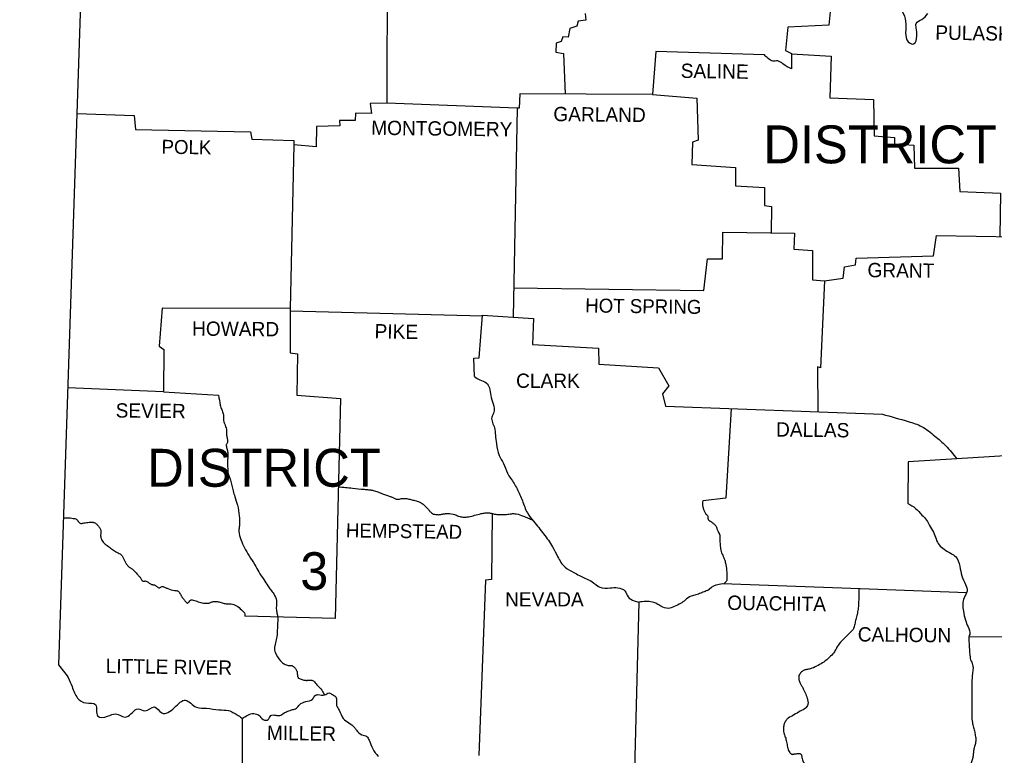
# Model space of a CAD drawing. Extents: x 982240 to 1103002, y 974866 to 1054902.
# Drawn here: x 1076997 to 1087558, y 1031353 to 1039317 of the extents above; entities that cross this region are included whole.
import ezdxf

# ---------------------------------------------------------------- set-up
doc = ezdxf.new("R2010")
doc.units = 0
doc.layers.add('1', color=7, linetype='Continuous')
doc.layers.add('Default', color=7, linetype='Continuous')

msp = doc.modelspace()

# ---------------------------------------------------------------- linework, layer by layer
at = {"layer": '1'}
msp.add_line((1082386, 1038358), (1082345, 1036097), dxfattribs=at)
for points in [[(1076997, 1048082), (1077743, 1042099), (1077419, 1032332)], [(1080980, 1039887), (1080975, 1038412), (1080795, 1038409), (1080810, 1038301), (1080637, 1038304), (1080633, 1038225), (1080464, 1038225), (1080468, 1038167), (1080216, 1038160), (1080212, 1037941), (1079967, 1037962), (1079928, 1036191), (1078542, 1036195), (1078509, 1035784), (1078560, 1035748), (1078556, 1035287), (1077518, 1035333)], [(1086498, 1039485), (1086238, 1039514), (1086249, 1039417), (1085778, 1039399), (1085763, 1039258), (1085320, 1039233), (1085295, 1038981), (1085360, 1038949), (1085360, 1038783)], [(1085065, 1038934), (1083888, 1038970), (1083855, 1038506), (1082415, 1038513), (1082409, 1038357)], [(1085716, 1036490), (1085918, 1036519), (1085932, 1036641), (1086051, 1036663), (1086058, 1036735), (1086897, 1036760), (1086930, 1036979), (1087790, 1036965)], [(1085716, 1036490), (1085673, 1035547), (1085641, 1035557), (1085644, 1035072)], [(1079928, 1036166), (1082011, 1036111)], [(1081926, 1035453), (1081918, 1035651), (1081976, 1035655), (1082012, 1036119), (1082566, 1036083), (1082552, 1035799), (1083268, 1035759), (1083272, 1035586), (1083920, 1035547), (1084032, 1035352), (1083963, 1035266), (1083996, 1035133), (1086343, 1035046)], [(1087675, 1034596), (1087148, 1034564)], [(1083704, 1033012), (1083657, 1031198), (1083171, 1031230), (1083168, 1031097), (1082527, 1031134)], [(1079409, 1031752), (1079416, 1028840), (1092610, 1028818)]]:
    msp.add_lwpolyline(points, dxfattribs=at)
for points in [[(1086498, 1039485), (1086559, 1039406), (1086595, 1039298), (1086595, 1039175), (1086624, 1039075), (1086681, 1039053), (1086717, 1039139), (1086710, 1039226), (1086710, 1039276), (1086771, 1039319), (1086836, 1039381)], [(1085360, 1038783), (1085266, 1038837), (1085212, 1038869), (1085155, 1038866), (1085108, 1038895), (1085065, 1038934)], [(1081926, 1035453), (1081983, 1035417), (1082052, 1035385), (1082088, 1035331), (1082102, 1035248), (1082127, 1035158), (1082134, 1035064), (1082113, 1035014), (1082142, 1034899), (1082152, 1034819), (1082163, 1034726), (1082192, 1034600), (1082239, 1034513), (1082282, 1034409), (1082354, 1034297), (1082415, 1034175), (1082444, 1034110), (1082498, 1033977), (1082566, 1033887), (1082674, 1033750), (1082772, 1033610), (1082826, 1033505), (1082908, 1033390), (1083002, 1033333), (1083121, 1033271), (1083196, 1033235), (1083283, 1033174), (1083394, 1033167), (1083477, 1033167), (1083553, 1033135), (1083589, 1033070), (1083654, 1033027), (1083704, 1033012)], [(1086343, 1035046), (1086624, 1034967), (1086768, 1034913), (1086912, 1034809), (1087030, 1034704), (1087148, 1034564)], [(1077419, 1032332), (1077523, 1032195), (1077566, 1032098), (1077627, 1031972), (1077717, 1031921), (1077822, 1031903), (1077843, 1031781), (1077951, 1031777), (1078038, 1031803), (1078157, 1031770), (1078283, 1031857), (1078355, 1031835), (1078459, 1031878), (1078538, 1031813), (1078675, 1031871), (1078797, 1031950), (1078913, 1031875), (1079024, 1031864), (1079157, 1031846), (1079262, 1031839), (1079355, 1031792), (1079402, 1031759), (1079409, 1031752)]]:
    msp.add_spline(points, degree=3, dxfattribs=at)
at = {"layer": 'Default'}
for points in [[(1083124, 1039384), (1083132, 1039309), (1083049, 1039301), (1083034, 1039244), (1082959, 1039222), (1082941, 1039125), (1082883, 1039129), (1082865, 1039078), (1082811, 1039060), (1082808, 1038963), (1082890, 1038949), (1082906, 1038511)], [(1085360, 1038947), (1085788, 1038920), (1085774, 1038470), (1086246, 1038452), (1086253, 1038059), (1086476, 1038041), (1086476, 1037973), (1086685, 1037959), (1086692, 1037707), (1087167, 1037707), (1087182, 1037458), (1087621, 1037437), (1087617, 1036968)], [(1083855, 1038506), (1084334, 1038466), (1084348, 1038013), (1084287, 1037991), (1084280, 1037750), (1084752, 1037717), (1084752, 1037519), (1085065, 1037501), (1085068, 1037303), (1085144, 1037293), (1085140, 1037008)], [(1082386, 1038358), (1080975, 1038412)], [(1077617, 1038301), (1078239, 1038279), (1078254, 1038128), (1079499, 1038103), (1079514, 1038023), (1079967, 1038009), (1079967, 1037962)], [(1082409, 1038357), (1082386, 1038358)], [(1082350, 1036414), (1084410, 1036385), (1084449, 1036727), (1084611, 1036727), (1084615, 1037015), (1085392, 1037005), (1085385, 1036832), (1085587, 1036817), (1085587, 1036501), (1085716, 1036490), (1085715, 1036457)], [(1079928, 1036191), (1079928, 1035712), (1080007, 1035698), (1080000, 1035251), (1080475, 1035215), (1080417, 1032836), (1079438, 1032861)], [(1078556, 1035287), (1079154, 1035251)], [(1084704, 1035107), (1084647, 1034139), (1084399, 1034110)], [(1087150, 1034564), (1086624, 1034531), (1086620, 1034081)], [(1082116, 1033972), (1082109, 1033257), (1082044, 1033250), (1081972, 1031353)], [(1084611, 1033214), (1086102, 1033160), (1087258, 1033115)], [(1087279, 1032638), (1088906, 1032641)]]:
    msp.add_lwpolyline(points, dxfattribs=at)
for points in [[(1079154, 1035251), (1079172, 1035143), (1079178, 1035120), (1079188, 1035097), (1079197, 1035073), (1079204, 1035050), (1079206, 1035032), (1079206, 1035014), (1079206, 1034996), (1079208, 1034978), (1079215, 1034951), (1079225, 1034924), (1079234, 1034897), (1079240, 1034870), (1079240, 1034830), (1079242, 1034810), (1079246, 1034790), (1079249, 1034771), (1079251, 1034751), (1079249, 1034740), (1079244, 1034729), (1079239, 1034719), (1079237, 1034708), (1079240, 1034686), (1079246, 1034665), (1079252, 1034643), (1079255, 1034621), (1079251, 1034557), (1079251, 1034503), (1079255, 1034413), (1079259, 1034392), (1079268, 1034373), (1079276, 1034353), (1079283, 1034333), (1079312, 1034215), (1079330, 1034153), (1079359, 1034060), (1079377, 1033945), (1079380, 1033858), (1079379, 1033838), (1079376, 1033819), (1079374, 1033799), (1079373, 1033779), (1079395, 1033689), (1079434, 1033599), (1079485, 1033513), (1079546, 1033415), (1079589, 1033340), (1079643, 1033257), (1079686, 1033189), (1079702, 1033167), (1079719, 1033146), (1079735, 1033124), (1079751, 1033102), (1079780, 1033030), (1079782, 1033005), (1079781, 1032980), (1079779, 1032955), (1079780, 1032929), (1079784, 1032906), (1079788, 1032883), (1079793, 1032859), (1079794, 1032836), (1079791, 1032731), (1079784, 1032638), (1079779, 1032605), (1079771, 1032573), (1079763, 1032540), (1079758, 1032508), (1079776, 1032447), (1079845, 1032357), (1079888, 1032332), (1079907, 1032327), (1079926, 1032327), (1079946, 1032325), (1079964, 1032317), (1079985, 1032294), (1080000, 1032267), (1080005, 1032248), (1080007, 1032227), (1080010, 1032208), (1080014, 1032199), (1080021, 1032191), (1080058, 1032174), (1080097, 1032166), (1080107, 1032165), (1080118, 1032166), (1080141, 1032168), (1080162, 1032168), (1080180, 1032159), (1080219, 1032116), (1080273, 1032058), (1080300, 1032008)], [(1080452, 1034261), (1080604, 1034247), (1080730, 1034233), (1080779, 1034229), (1080804, 1034226), (1080816, 1034224), (1080828, 1034222), (1080853, 1034214), (1080879, 1034205), (1080928, 1034186), (1081018, 1034153), (1081033, 1034147), (1081047, 1034141), (1081061, 1034134), (1081076, 1034128), (1081100, 1034126), (1081124, 1034130), (1081149, 1034135), (1081173, 1034135), (1081215, 1034128), (1081256, 1034117), (1081304, 1034105), (1081327, 1034096), (1081339, 1034091), (1081350, 1034085), (1081386, 1034056), (1081418, 1034024), (1081428, 1034012), (1081438, 1034000), (1081461, 1033977), (1081481, 1033966), (1081502, 1033961), (1081544, 1033959), (1081561, 1033961), (1081578, 1033965), (1081595, 1033968), (1081612, 1033970), (1081695, 1033963), (1081719, 1033956), (1081742, 1033947), (1081765, 1033939), (1081789, 1033934), (1081808, 1033932), (1081827, 1033932), (1081864, 1033937), (1081926, 1033952), (1081998, 1033970), (1082042, 1033977), (1082065, 1033978), (1082088, 1033977), (1082105, 1033974), (1082122, 1033970), (1082139, 1033966), (1082156, 1033963), (1082201, 1033960), (1082246, 1033959), (1082272, 1033961), (1082298, 1033965), (1082324, 1033969), (1082337, 1033970), (1082350, 1033970), (1082377, 1033967), (1082455, 1033944), (1082507, 1033922), (1082557, 1033899)], [(1084399, 1034110), (1084395, 1034076), (1084396, 1034059), (1084399, 1034042), (1084403, 1034025), (1084409, 1034009), (1084416, 1033993), (1084424, 1033977), (1084430, 1033969), (1084436, 1033962), (1084443, 1033956), (1084449, 1033948), (1084453, 1033937), (1084453, 1033924), (1084455, 1033912), (1084457, 1033906), (1084460, 1033901), (1084468, 1033895), (1084476, 1033890), (1084484, 1033885), (1084492, 1033880), (1084499, 1033875), (1084505, 1033870), (1084518, 1033860), (1084530, 1033850), (1084535, 1033843), (1084539, 1033837), (1084546, 1033822), (1084552, 1033806), (1084558, 1033791), (1084564, 1033775), (1084574, 1033756), (1084579, 1033746), (1084581, 1033741), (1084582, 1033736), (1084584, 1033723), (1084584, 1033711), (1084583, 1033698), (1084582, 1033685), (1084584, 1033660), (1084586, 1033635), (1084589, 1033604), (1084591, 1033589), (1084593, 1033574), (1084601, 1033546), (1084614, 1033519), (1084626, 1033493), (1084636, 1033466), (1084647, 1033423), (1084654, 1033387), (1084658, 1033325), (1084659, 1033307), (1084659, 1033289), (1084659, 1033271), (1084658, 1033262), (1084658, 1033253), (1084655, 1033243), (1084648, 1033232), (1084628, 1033213)], [(1086620, 1034081), (1086703, 1034027), (1086771, 1033955), (1086822, 1033901), (1086854, 1033840), (1086897, 1033768), (1086958, 1033631), (1087012, 1033585), (1087088, 1033538), (1087135, 1033505), (1087182, 1033401), (1087203, 1033297), (1087243, 1033203), (1087261, 1033131), (1087228, 1033059), (1087221, 1032915), (1087243, 1032818), (1087271, 1032746), (1087289, 1032663), (1087279, 1032638)], [(1077471, 1033921), (1077508, 1033924), (1077545, 1033923), (1077580, 1033919), (1077609, 1033912), (1077622, 1033902), (1077634, 1033886), (1077648, 1033871), (1077663, 1033865), (1077696, 1033869), (1077753, 1033876), (1077767, 1033877), (1077780, 1033877), (1077794, 1033876), (1077807, 1033873), (1077819, 1033867), (1077829, 1033860), (1077838, 1033850), (1077847, 1033840), (1077858, 1033827), (1077867, 1033813), (1077875, 1033798), (1077879, 1033783), (1077880, 1033769), (1077878, 1033756), (1077876, 1033742), (1077876, 1033729), (1077879, 1033707), (1077884, 1033694), (1077889, 1033682), (1077905, 1033660), (1077948, 1033624), (1077995, 1033588), (1078038, 1033559), (1078047, 1033554), (1078057, 1033549), (1078078, 1033540), (1078096, 1033528), (1078110, 1033513), (1078117, 1033498), (1078146, 1033441), (1078162, 1033416), (1078171, 1033405), (1078182, 1033394), (1078192, 1033386), (1078204, 1033379), (1078215, 1033373), (1078225, 1033365), (1078272, 1033315), (1078293, 1033293), (1078303, 1033281), (1078311, 1033267), (1078319, 1033254), (1078324, 1033248), (1078329, 1033243), (1078338, 1033239), (1078349, 1033240), (1078359, 1033241), (1078369, 1033239), (1078383, 1033231), (1078396, 1033223), (1078409, 1033214), (1078423, 1033207), (1078433, 1033203), (1078443, 1033201), (1078453, 1033199), (1078463, 1033196), (1078474, 1033190), (1078484, 1033181), (1078494, 1033173), (1078506, 1033167), (1078516, 1033168), (1078527, 1033174), (1078538, 1033181), (1078549, 1033181), (1078562, 1033176), (1078576, 1033171), (1078589, 1033165), (1078603, 1033160), (1078675, 1033138), (1078685, 1033137), (1078695, 1033136), (1078710, 1033134), (1078712, 1033132), (1078715, 1033131), (1078730, 1033116), (1078741, 1033099), (1078750, 1033080), (1078755, 1033071), (1078761, 1033063), (1078784, 1033033), (1078795, 1033019), (1078808, 1033005), (1078814, 1033002), (1078821, 1033004), (1078835, 1033017), (1078850, 1033032), (1078858, 1033036), (1078866, 1033037), (1078892, 1033030), (1078919, 1033021), (1078946, 1033011), (1078974, 1033005), (1079008, 1033001), (1079042, 1033001), (1079058, 1033005), (1079073, 1033011), (1079088, 1033016), (1079103, 1033019), (1079150, 1033016), (1079172, 1033011), (1079193, 1033005), (1079215, 1032999), (1079237, 1032994), (1079250, 1032993), (1079263, 1032994), (1079277, 1032995), (1079290, 1032994), (1079348, 1032973), (1079402, 1032929), (1079438, 1032883), (1079438, 1032861)], [(1084449, 1033138), (1084423, 1033128), (1084377, 1033109), (1084323, 1033091), (1084273, 1033077), (1084208, 1033034), (1084158, 1032998), (1084089, 1032965), (1084024, 1032944), (1083945, 1032969), (1083902, 1032994), (1083855, 1033012), (1083704, 1033012)], [(1084449, 1033138), (1084543, 1033199), (1084611, 1033214)], [(1086089, 1033160), (1086087, 1033048), (1086085, 1032992), (1086083, 1032965), (1086080, 1032937), (1086069, 1032880), (1086055, 1032825), (1086045, 1032774), (1086039, 1032749), (1086035, 1032736), (1086032, 1032730), (1086030, 1032724), (1086019, 1032708), (1086005, 1032693), (1085976, 1032667), (1085947, 1032638), (1085918, 1032609), (1085864, 1032544), (1085851, 1032525), (1085841, 1032505), (1085830, 1032484), (1085817, 1032465), (1085770, 1032415), (1085709, 1032364), (1085648, 1032328), (1085580, 1032296), (1085561, 1032290), (1085542, 1032286), (1085523, 1032283), (1085504, 1032278), (1085474, 1032263), (1085461, 1032252), (1085455, 1032245), (1085450, 1032238), (1085440, 1032217), (1085437, 1032195), (1085446, 1032152), (1085461, 1032121), (1085477, 1032091), (1085493, 1032060), (1085508, 1032029), (1085529, 1031972), (1085534, 1031955), (1085537, 1031938), (1085538, 1031920), (1085536, 1031903), (1085511, 1031864), (1085454, 1031831), (1085385, 1031792), (1085324, 1031756), (1085309, 1031744), (1085298, 1031730), (1085288, 1031713), (1085281, 1031695), (1085271, 1031653), (1085274, 1031612), (1085280, 1031587), (1085288, 1031563), (1085296, 1031539), (1085302, 1031515), (1085308, 1031486), (1085313, 1031457), (1085327, 1031406), (1085340, 1031384), (1085349, 1031374), (1085354, 1031371), (1085360, 1031367), (1085369, 1031365), (1085378, 1031366), (1085387, 1031369), (1085396, 1031371), (1085404, 1031371), (1085412, 1031372), (1085428, 1031375), (1085445, 1031374), (1085453, 1031372), (1085457, 1031370), (1085461, 1031367), (1085466, 1031359), (1085468, 1031349), (1085472, 1031331), (1085486, 1031284), (1085497, 1031272), (1085513, 1031264), (1085529, 1031256), (1085540, 1031245), (1085542, 1031236), (1085544, 1031227), (1085545, 1031217), (1085547, 1031209), (1085561, 1031174), (1085580, 1031140), (1085591, 1031126), (1085604, 1031113), (1085634, 1031093), (1085673, 1031079), (1085756, 1031054), (1085799, 1031043), (1085805, 1031040), (1085817, 1031023), (1085822, 1030988), (1085828, 1030955), (1085835, 1030943), (1085846, 1030939), (1085875, 1030939), (1085904, 1030942), (1085947, 1030949), (1085983, 1030948), (1086001, 1030942), (1086010, 1030937), (1086019, 1030931), (1086038, 1030911), (1086051, 1030888), (1086060, 1030870), (1086067, 1030852), (1086075, 1030834), (1086084, 1030816), (1086103, 1030789), (1086113, 1030778)], [(1087279, 1032638), (1087281, 1032582), (1087285, 1032526), (1087293, 1032415), (1087299, 1032387), (1087311, 1032361), (1087321, 1032334), (1087324, 1032320), (1087325, 1032307), (1087324, 1032278), (1087320, 1032249), (1087317, 1032220), (1087315, 1032191), (1087311, 1032080), (1087311, 1031979), (1087311, 1031882), (1087311, 1031781), (1087318, 1031709), (1087324, 1031683), (1087330, 1031657), (1087337, 1031631), (1087343, 1031605), (1087352, 1031556), (1087355, 1031532), (1087354, 1031507), (1087351, 1031484), (1087345, 1031461), (1087338, 1031437), (1087333, 1031414), (1087330, 1031392), (1087328, 1031371), (1087326, 1031349), (1087322, 1031327), (1087315, 1031306), (1087308, 1031284), (1087300, 1031263), (1087293, 1031241), (1087268, 1031144), (1087239, 1031018), (1087228, 1030976), (1087221, 1030955), (1087214, 1030935), (1087203, 1030912), (1087190, 1030891), (1087176, 1030870), (1087164, 1030849), (1087155, 1030829), (1087147, 1030809), (1087140, 1030789), (1087131, 1030769), (1087120, 1030756), (1087105, 1030745), (1087090, 1030734), (1087085, 1030727), (1087081, 1030719), (1087073, 1030676), (1087074, 1030633), (1087076, 1030613), (1087079, 1030593), (1087082, 1030573), (1087084, 1030553), (1087084, 1030535), (1087081, 1030517), (1087078, 1030499), (1087077, 1030481), (1087084, 1030447), (1087102, 1030413), (1087114, 1030398), (1087127, 1030384), (1087154, 1030366)], [(1079409, 1031752), (1079535, 1031806), (1079589, 1031788), (1079636, 1031741), (1079690, 1031741), (1079719, 1031785), (1079773, 1031788), (1079816, 1031785), (1079863, 1031813), (1079902, 1031831), (1079956, 1031849), (1079996, 1031864), (1080032, 1031903), (1080097, 1031936), (1080172, 1031961), (1080194, 1031997), (1080230, 1032011), (1080302, 1032008), (1080349, 1032029), (1080388, 1032011), (1080424, 1031986), (1080432, 1031893), (1080460, 1031842), (1080504, 1031752), (1080565, 1031705), (1080622, 1031659), (1080644, 1031630), (1080705, 1031576), (1080759, 1031558), (1080784, 1031518), (1080824, 1031425), (1080882, 1031342)]]:
    msp.add_spline(points, degree=3, dxfattribs=at)

# ---------------------------------------------------------------- texts
for s, height, rotation, p in [('PULASKI', 154.8, 359.053, (1086915, 1039100)), ('SALINE', 154.8, 359.1491, (1084158, 1038686)), ('GARLAND', 154.8, 359.3657, (1082779, 1038218)), ('MONTGOMERY', 154.8, 359.2944, (1080806, 1038070)), ('POLK', 151.2, 359.2152, (1078535, 1037865)), ('GRANT', 154.8, 359.4032, (1086181, 1036529)), ('HOT SPRING', 151.2, 359.2216, (1083124, 1036148)), ('HOWARD', 154.8, 359.5144, (1078866, 1035896)), ('PIKE', 154.8, 359.0451, (1080842, 1035867)), ('SEVIER', 154.8, 359.427, (1078038, 1035010)), ('DALLAS', 154.8, 359.2461, (1085191, 1034805)), ('HEMPSTEAD', 151.2, 359.1885, (1080532, 1033714)), ('OUACHITA', 154.8, 359.2043, (1084662, 1032929)), ('CALHOUN', 154.8, 359.3634, (1086076, 1032587)), ('LITTLE RIVER', 154.82, 359.1697, (1077930, 1032245)), ('MILLER', 154.8, 359.1319, (1079676, 1031522))]:
    msp.add_text(s, height=height, rotation=rotation, dxfattribs=at).set_placement(p)
for s, height, p in [('DISTRICT 6', 410.4, (1085054, 1037761)), ('CLARK', 154.8, (1082376, 1035331)), ('DISTRICT', 410.4, (1078380, 1034261)), ('3', 407, (1080039, 1033145)), ('NEVADA', 154.8, (1082257, 1032965))]:
    msp.add_text(s, height=height, dxfattribs=at).set_placement(p)

doc.saveas('drawing.dxf')
